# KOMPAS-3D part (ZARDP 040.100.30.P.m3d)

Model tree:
1. Плоскость XY
2. Плоскость ZX
3. Плоскость ZY
4. Ось X
5. Ось Y
6. Ось Z
7. Начало координат
8. Булева операция:1
9. Булева операция:2
10. Булева операция:3
11. Булева операция:4
12. Булева операция:5
13. Булева операция:6
